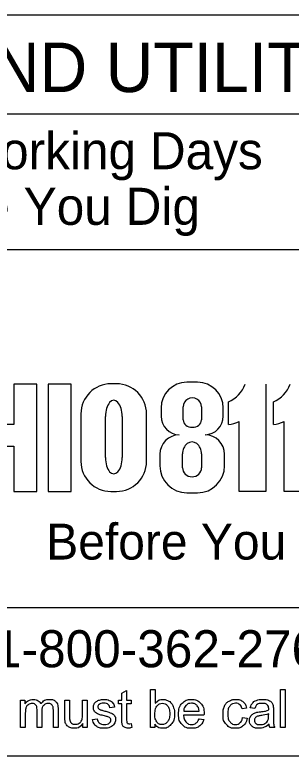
# Model space of a CAD drawing. Extents: x 0 to 34, y 0 to 22.
# Drawn here: x 5.253 to 6.372, y 2.257 to 5.257 of the extents above; entities that cross this region are included whole.
import ezdxf

# ---------------------------------------------------------------- set-up
doc = ezdxf.new("R2010")
doc.units = 0
doc.layers.add('SH_Data', color=7, linetype='Continuous')

msp = doc.modelspace()

# ---------------------------------------------------------------- linework, layer by layer
at = {"layer": 'SH_Data'}
for p, q in [((3.25, 5.2574), (8, 5.2574)), ((3.25, 4.8574), (8, 4.8574)), ((3.25, 4.3074), (8, 4.3074)), ((5.6649, 3.7644), (5.6425, 3.7644)), ((5.9932, 3.7704), (5.9488, 3.7704)), ((6.2693, 3.7631), (6.2693, 3.3286)), ((6.1178, 3.5992), (6.1178, 3.6918)), ((6.2997, 3.5992), (6.2997, 3.6918)), ((5.8451, 3.6667), (5.8451, 3.6337)), ((5.935, 3.6183), (5.935, 3.6716)), ((6.0085, 3.6716), (6.0085, 3.6183)), ((6.0968, 3.6337), (6.0968, 3.6667)), ((5.521, 3.6429), (5.521, 3.4501)), ((5.62, 3.4655), (5.62, 3.6317)), ((5.6876, 3.6317), (5.6876, 3.4655)), ((5.7864, 3.4501), (5.7864, 3.6429)), ((6.1617, 3.3286), (6.1617, 3.6119)), ((6.3436, 3.3286), (6.3436, 3.6119)), ((5.9317, 3.4248), (5.9317, 3.4803)), ((6.009, 3.4803), (6.009, 3.4248)), ((5.8401, 3.4791), (5.8401, 3.4329)), ((6.1023, 3.4329), (6.1023, 3.4791)), ((5.6425, 3.3286), (5.6649, 3.3286)), ((5.95, 3.3229), (5.9924, 3.3229)), ((6.2693, 3.3286), (6.1617, 3.3286)), ((6.4512, 3.3286), (6.3436, 3.3286)), ((8, 2.8574), (3.25, 2.8574)), ((8, 2.2574), (3.25, 2.2574))]:
    msp.add_line(p, q, dxfattribs=at)
for points in [[(5.1805, 3.5123), (5.2497, 3.5123), (5.2497, 3.3286), (5.342, 3.3286), (5.342, 3.7631), (5.2497, 3.7631), (5.2497, 3.5992), (5.1805, 3.5992), (5.1805, 3.7631)], [(5.3882, 3.3286), (5.4815, 3.3286), (5.4815, 3.7631), (5.3882, 3.7631), (5.3882, 3.3286)], [(5.9187, 3.5577), (5.9187, 3.5577)], [(6.0237, 3.5577), (6.0237, 3.5577)], [(5.6868, 2.4054), (5.6868, 2.4697), (5.6728, 2.4697), (5.6728, 2.4844), (5.6868, 2.4844), (5.6868, 2.512), (5.7057, 2.5234), (5.7057, 2.4844), (5.7246, 2.4844), (5.7246, 2.4697), (5.7057, 2.4697), (5.7057, 2.4043)], [(5.8202, 2.3728), (5.8027, 2.3728), (5.8027, 2.5268), (5.8216, 2.5268), (5.8216, 2.4719)], [(6.3286, 2.3728), (6.3286, 2.5268), (6.3475, 2.5268), (6.3475, 2.3728), (6.3286, 2.3728)], [(5.2769, 2.3728), (5.2769, 2.4844), (5.2938, 2.4844), (5.2938, 2.4686)], [(5.4557, 2.4153), (5.4557, 2.4844), (5.4746, 2.4844), (5.4746, 2.4225)], [(5.5271, 2.4246), (5.5271, 2.4844), (5.546, 2.4844), (5.546, 2.3728), (5.5291, 2.3728)], [(5.2958, 2.4306), (5.2958, 2.3728), (5.2769, 2.3728)], [(5.3621, 2.4376), (5.3621, 2.3728), (5.3432, 2.3728), (5.3432, 2.4452)], [(5.4282, 2.4493), (5.4282, 2.3728), (5.4093, 2.3728), (5.4093, 2.443)], [(5.6567, 2.4555), (5.6382, 2.453)], [(5.9367, 2.4392), (5.999, 2.4392)], [(6.1915, 2.4515), (6.1731, 2.4487)], [(6.2248, 2.45), (6.2063, 2.4525)], [(6.2997, 2.4447), (6.2997, 2.4195)], [(5.5681, 2.4061), (5.5868, 2.409)], [(6.0188, 2.4237), (5.9356, 2.4237)], [(5.9988, 2.4088), (6.0183, 2.4063)], [(6.1747, 2.4136), (6.1933, 2.4111)], [(6.2806, 2.4218), (6.2807, 2.4287)], [(5.5291, 2.3728), (5.5291, 2.3892)], [(5.7246, 2.3896), (5.7273, 2.3729)], [(5.8202, 2.3867), (5.8202, 2.3728)], [(6.3057, 2.3728), (6.286, 2.3728)]]:
    msp.add_lwpolyline(points, dxfattribs=at)
for centre, radius, start, end in [((5.6425, 3.6429), 0.1215, 90, 180), ((5.6649, 3.6429), 0.1215, 0, 90), ((5.9488, 3.6667), 0.1036, 90, 180), ((5.9932, 3.6667), 0.1036, 0, 90), ((6.0717, 3.8027), 0.1202, 292.5572, 340.7355), ((6.2536, 3.8027), 0.1202, 292.5572, 340.7355), ((5.9212, 3.6337), 0.076, 180, 268.1442), ((6.0208, 3.6337), 0.076, 272.2058, 0), ((6.1069, 3.7188), 0.1202, 275.1733, 297.0931), ((6.2889, 3.7188), 0.1202, 275.1733, 297.0931), ((5.9187, 3.4791), 0.0786, 90, 180), ((6.0237, 3.4791), 0.0786, 0, 90), ((5.6425, 3.4501), 0.1215, 180, 270), ((5.6649, 3.4501), 0.1215, 270, 0), ((5.95, 3.4329), 0.1099, 180, 270), ((5.9924, 3.4329), 0.1099, 270, 0)]:
    msp.add_arc(centre, radius, start, end, dxfattribs=at)
for centre, major_axis, ratio, start_param, end_param in [((5.6538, 3.6317), (0, 0.0657), 0.514403, 4.712389, 7.853982), ((5.9717, 3.6716), (0.0368, 0), 0.969373, 0, 3.141593), ((5.9717, 3.6183), (0.0368, 0), 0.818453, 3.141593, 6.283185), ((5.9704, 3.4803), (0, 0.0486), 0.794529, 4.712389, 7.853982), ((5.6538, 3.4655), (0, 0.0657), 0.514403, 1.570796, 4.712389), ((5.9704, 3.4248), (0.0386, 0), 0.959837, 3.141593, 6.283185)]:
    msp.add_ellipse(centre, major_axis=major_axis, ratio=ratio, start_param=start_param, end_param=end_param, dxfattribs=at)
for points, degree in [([(5.2938, 2.4686), (5.299, 2.4768), (5.3077, 2.4818), (5.3165, 2.4869), (5.3276, 2.4869), (5.34, 2.4869), (5.348, 2.4817), (5.3559, 2.4765), (5.3591, 2.4673), (5.3724, 2.4869), (5.3937, 2.4869), (5.4103, 2.4869), (5.4192, 2.4777), (5.4282, 2.4685), (5.4282, 2.4493)], 3), ([(5.3432, 2.4452), (5.3432, 2.4578), (5.3386, 2.4641), (5.3339, 2.4704), (5.3234, 2.4704), (5.3154, 2.4704), (5.3086, 2.4662), (5.3019, 2.462), (5.2988, 2.4539), (5.2958, 2.4458), (5.2958, 2.4306)], 3), ([(5.4093, 2.443), (5.4093, 2.4544), (5.4074, 2.4593), (5.4056, 2.4643), (5.4008, 2.4674), (5.3959, 2.4704), (5.3894, 2.4704), (5.3776, 2.4704), (5.3699, 2.4626), (5.3621, 2.4548), (5.3621, 2.4376)], 3), ([(5.6382, 2.453), (5.6369, 2.4617), (5.6309, 2.4665), (5.6248, 2.4714), (5.6138, 2.4714), (5.6007, 2.4714), (5.5952, 2.467), (5.5896, 2.4627), (5.5896, 2.4569), (5.5896, 2.4533), (5.5919, 2.4503), (5.5942, 2.4473), (5.5992, 2.4453), (5.602, 2.4442), (5.6159, 2.4404), (5.636, 2.4351), (5.6439, 2.4317), (5.6519, 2.4282), (5.6564, 2.4217), (5.6609, 2.4152), (5.6609, 2.4056), (5.6609, 2.3961), (5.6554, 2.3878), (5.6499, 2.3794), (5.6395, 2.3749), (5.6291, 2.3703), (5.6159, 2.3703), (5.5941, 2.3703), (5.5827, 2.3793), (5.5713, 2.3884), (5.5681, 2.4061)], 3), ([(5.5868, 2.409), (5.5883, 2.3978), (5.5956, 2.3918), (5.6028, 2.3858), (5.6158, 2.3858), (5.6288, 2.3858), (5.6351, 2.3911), (5.6415, 2.3964), (5.6415, 2.4036), (5.6415, 2.41), (5.6359, 2.4137), (5.632, 2.4162), (5.6165, 2.4201), (5.5957, 2.4253), (5.5876, 2.4292), (5.5796, 2.433), (5.5754, 2.4398), (5.5713, 2.4465), (5.5713, 2.4547), (5.5713, 2.4622), (5.5747, 2.4685), (5.5781, 2.4749), (5.584, 2.4791), (5.5884, 2.4823), (5.5961, 2.4846), (5.6037, 2.4869), (5.6124, 2.4869), (5.6256, 2.4869), (5.6355, 2.4831), (5.6455, 2.4793), (5.6502, 2.4728), (5.6549, 2.4663), (5.6567, 2.4555)], 3), ([(5.82, 2.4294), (5.82, 2.4093), (5.8254, 2.4004), (5.8344, 2.3858), (5.8496, 2.3858), (5.8619, 2.3858), (5.871, 2.3966), (5.88, 2.4073), (5.88, 2.4287), (5.88, 2.4505), (5.8713, 2.4609), (5.8627, 2.4714), (5.8504, 2.4714), (5.838, 2.4714), (5.829, 2.4606), (5.82, 2.4498), (5.82, 2.4294)], 3), ([(5.8216, 2.4719), (5.8336, 2.4869), (5.8522, 2.4869), (5.8625, 2.4869), (5.8717, 2.4827), (5.8809, 2.4786), (5.8868, 2.471), (5.8927, 2.4635), (5.8961, 2.4529), (5.8995, 2.4423), (5.8995, 2.4303), (5.8995, 2.4016), (5.8853, 2.3859), (5.8711, 2.3703), (5.8512, 2.3703), (5.8315, 2.3703), (5.8202, 2.3867)], 3), ([(6.0183, 2.4063), (6.0137, 2.3892), (6.0012, 2.3797), (5.9887, 2.3703), (5.9693, 2.3703), (5.9448, 2.3703), (5.9305, 2.3854), (5.9161, 2.4004), (5.9161, 2.4276), (5.9161, 2.4558), (5.9306, 2.4713), (5.9451, 2.4869), (5.9682, 2.4869), (5.9906, 2.4869), (6.0048, 2.4716), (6.019, 2.4564), (6.019, 2.4287), (6.019, 2.4271), (6.0188, 2.4237)], 3), ([(5.999, 2.4392), (5.9977, 2.4533), (5.9919, 2.4604), (5.9828, 2.4714), (5.9684, 2.4714), (5.9554, 2.4714), (5.9465, 2.4626), (5.9376, 2.4539), (5.9367, 2.4392)], 3), ([(6.1933, 2.4111), (6.1902, 2.392), (6.1777, 2.3811), (6.1651, 2.3703), (6.1468, 2.3703), (6.1239, 2.3703), (6.11, 2.3853), (6.0961, 2.4002), (6.0961, 2.4282), (6.0961, 2.4462), (6.1021, 2.4598), (6.1081, 2.4733), (6.1203, 2.4801), (6.1325, 2.4869), (6.1469, 2.4869), (6.1651, 2.4869), (6.1767, 2.4777), (6.1882, 2.4685), (6.1915, 2.4515)], 3), ([(6.1731, 2.4487), (6.1704, 2.46), (6.1638, 2.4657), (6.1571, 2.4714), (6.1477, 2.4714), (6.1334, 2.4714), (6.1245, 2.4611), (6.1156, 2.4509), (6.1156, 2.4287), (6.1156, 2.4062), (6.1242, 2.396), (6.1328, 2.3858), (6.1467, 2.3858), (6.1578, 2.3858), (6.1653, 2.3926), (6.1727, 2.3994), (6.1747, 2.4136)], 3), ([(6.2822, 2.3865), (6.2717, 2.3776), (6.262, 2.374), (6.2523, 2.3703), (6.2411, 2.3703), (6.2227, 2.3703), (6.2129, 2.3793), (6.203, 2.3882), (6.203, 2.4022), (6.203, 2.4104), (6.2067, 2.4171), (6.2105, 2.4239), (6.2165, 2.428), (6.2225, 2.4321), (6.2301, 2.4342), (6.2357, 2.4357), (6.2469, 2.437), (6.2698, 2.4398), (6.2806, 2.4435), (6.2807, 2.4474), (6.2807, 2.4485), (6.2807, 2.4601), (6.2754, 2.4648), (6.2681, 2.4712), (6.2539, 2.4712), (6.2406, 2.4712), (6.2342, 2.4666), (6.2279, 2.4619), (6.2248, 2.45)], 3), ([(6.2063, 2.4525), (6.2088, 2.4643), (6.2146, 2.4717), (6.2204, 2.479), (6.2313, 2.4829), (6.2422, 2.4869), (6.2566, 2.4869), (6.2709, 2.4869), (6.2798, 2.4835), (6.2887, 2.4801), (6.2929, 2.475), (6.2971, 2.4699), (6.2988, 2.4621), (6.2997, 2.4573), (6.2997, 2.4447)], 3), ([(5.5291, 2.3892), (5.5161, 2.3703), (5.4938, 2.3703), (5.4839, 2.3703), (5.4753, 2.3741), (5.4668, 2.3779), (5.4626, 2.3836), (5.4585, 2.3893), (5.4568, 2.3976), (5.4557, 2.4032), (5.4557, 2.4153)], 3), ([(5.4746, 2.4225), (5.4746, 2.4077), (5.4757, 2.4026), (5.4775, 2.3951), (5.4833, 2.3909), (5.489, 2.3866), (5.4975, 2.3866), (5.506, 2.3866), (5.5135, 2.391), (5.5209, 2.3953), (5.524, 2.4028), (5.5271, 2.4103), (5.5271, 2.4246)], 3), ([(5.7273, 2.3729), (5.7193, 2.3712), (5.713, 2.3712), (5.7027, 2.3712), (5.6971, 2.3745), (5.6914, 2.3778), (5.6891, 2.3831), (5.6868, 2.3884), (5.6868, 2.4054)], 3), ([(5.7057, 2.4043), (5.7057, 2.3962), (5.7067, 2.3939), (5.7077, 2.3916), (5.7099, 2.3902), (5.7121, 2.3888), (5.7163, 2.3888), (5.7195, 2.3888), (5.7246, 2.3896)], 3), ([(5.9356, 2.4237), (5.9367, 2.4053), (5.946, 2.3956), (5.9554, 2.3858), (5.9694, 2.3858), (5.9798, 2.3858), (5.9871, 2.3913), (5.9945, 2.3968), (5.9988, 2.4088)], 3), ([(6.2807, 2.4287), (6.2704, 2.4246), (6.2498, 2.4216), (6.2381, 2.4199), (6.2333, 2.4178), (6.2284, 2.4157), (6.2258, 2.4117), (6.2232, 2.4077), (6.2232, 2.4027), (6.2232, 2.3952), (6.2289, 2.3901), (6.2346, 2.3851), (6.2457, 2.3851), (6.2566, 2.3851), (6.2651, 2.3899), (6.2736, 2.3946), (6.2776, 2.4029), (6.2806, 2.4093), (6.2806, 2.4218)], 3), ([(6.2997, 2.4195), (6.2997, 2.3932), (6.3009, 2.3862), (6.3021, 2.3792), (6.3057, 2.3728)], 3), ([(6.286, 2.3728), (6.2831, 2.3786), (6.2822, 2.3865)], 2)]:
    msp.add_open_spline(points, degree=degree, dxfattribs=at)

# ---------------------------------------------------------------- texts
for s, height, p in [('UNDERGROUND UTILITIES', 0.2, (3.4069, 4.9448)), ('Contact Two Working Days', 0.15, (3.8267, 4.6325)), ('Before You Dig', 0.15, (4.6423, 4.4075)), ('Before You Dig', 0.1452, (5.3804, 3.0531)), ('OHIO811, 8-1-1, or 1-800-362-2764', 0.15, (3.3964, 2.6172))]:
    msp.add_text(s, height=height, dxfattribs=at).set_placement(p)

doc.saveas('drawing.dxf')
